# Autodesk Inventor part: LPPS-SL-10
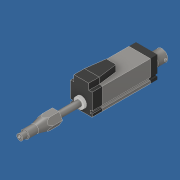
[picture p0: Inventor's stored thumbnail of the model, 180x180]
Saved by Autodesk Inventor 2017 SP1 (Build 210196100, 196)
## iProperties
Created: 2016-12
Part Number: LPPS-SL-10
Material: Stainless Steel
Document SubType Name: Modeling
Designer: JN
Density: 8 g/cm^3
Appearance: Stainless - Brushed
Author: JN
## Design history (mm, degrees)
sketch "Sketch1"
  geometry: C1 r 2.54 at (0, 0)
  constraints: 1 centre point, 1 other
  dimensions: "d0" = 5.08 diameter of C1
extrude "Extrusion1" new body sketch "Sketch1" distance "d1" = 4.572; taper "d2" = 0 deg
sketch "Sketch2"
  geometry: C1 r 3.48 at (0, 0)
  constraints: 1 centre point
  dimensions: "d3" = 6.9596 diameter of C1
extrude "Extrusion2" join sketch "Sketch2" distance "d4" = 8.2042; taper "d5" = 0 deg
workaxis "Work Axis1"
revolve "Revolution2" stored, may be unused: angle "d8" = 90 deg
sketch "Sketch7"
  geometry: L1 (-5.778, 0)-(-2.889, 5.004); L2 (-2.889, 5.004)-(2.889, 5.004); L3 (2.889, 5.004)-(5.778, 0); L4 (5.778, 0)-(2.889, -5.004); L5 (2.889, -5.004)-(-2.889, -5.004); L6 (-2.889, -5.004)-(-5.778, 0); L7 (0, 0)-(0, 8.469); L8 (-0.303, -0.272)-(8.166, -0.272); L9 (0, -3.48)-(0, 0)
  constraints: 18 end point, 3 perpendicular, 1 horizontal, 1 vertical alignment, 14 other
  dimensions: "d20" = 90 deg angle of L8 L7; "d23" = 10.0076 distance between parallel lines of L5 L2
extrude "Extrusion4" join sketch "Sketch7" distance "d21" = 18.03974; taper "d22" = 0 deg
sketch "Sketch8"
  geometry: L1 (3.48, -4.572)-(3.48, -12.776) reference; L2 (0, 1.416)-(0, -21.685); L3 (0, -12.776)-(0, -30.816) reference; L4 (0, 9.356)-(0, -46.226) reference; L5 (5.004, -30.816)-(-5.004, -30.816); L6 (5.004, -30.816)-(0, -30.816) reference; L7 (0, -30.816)-(-5.004, -30.816) reference; L8 (-5.004, -12.776)-(-5.004, -30.816) reference; L9 (-5.004, -30.816)-(-5.004, -12.776); L10 (4.859, -30.943)-(-0.272, -30.943); L11 (-3.48, -12.776)-(3.48, -12.776) reference; L12 (3.48, -4.572)-(3.48, -12.776) reference; L13 (3.48, -12.776)-(3.481, -12.776); L14 (3.481, -12.776)-(9.456, -38.286); L15 (3.481, -12.776)-(9.456, -12.776); L16 (9.456, -38.286)-(9.456, -12.776); A1 r 1.416 centre (0, 0) between (1.416, 0) and (-1.416, 0) reference; 1 further point
  constraints: 16 end point, 2 collinear, 1 horizontal, 1 perpendicular, 1 point on circle, 1 point on line, 1 vertical
revolve "Revolution9" sketch "Sketch8" stored, may be unused: angle "d35" = 90 deg
sketch "Sketch9"
  geometry: C1 r 2.54 at (0, 0)
  constraints: 1 centre point
  dimensions: "d36" = 5.08 diameter of C1
extrude "Extrusion5" join sketch "Sketch9" distance "d37" = 19.812 (= Stroke); taper "d38" = 0 deg
sketch "Sketch10"
  geometry: C1 r 2.54 at (0, 0) reference; C2 r 4.521 at (0, 0)
  constraints: 1 centre point, 1 coincident
  dimensions: "d39" = 9.0424 diameter of C2
extrude "Extrusion6" join sketch "Sketch10" distance "d40" = 2; taper "d41" = 0 deg
sketch "Sketch11"
  geometry: L1 (-9.143, 16.927)-(9.145, 16.927); L2 (9.145, -6.949)-(-9.143, -6.949); L3 (-9.143, -6.949)-(-9.143, 16.927); L4 (-5.778, 0)-(-2.889, -5.004) reference; L5 (5.778, 0)-(2.889, 5.004) reference; L6 (-5.778, 0)-(5.778, 0); L7 (2.889, 5.004)-(-2.889, 5.004) reference; L8 (0, 5.004)-(0, -5.004); L9 (-2.889, -5.004)-(2.889, -5.004) reference; L10 (9.145, -6.949)-(9.145, -4.663); L11 (9.145, -4.663)-(7.621, -4.663); L12 (7.621, -4.663)-(7.621, -2.377); L13 (7.621, -2.377)-(9.145, -2.377); L14 (9.145, 16.927)-(9.145, -2.377); L15 (9.145, -4.663)-(9.145, -6.949); L16 (-9.143, -2.377)-(-7.619, -2.377); L17 (-7.619, -2.377)-(-7.619, -4.663); L18 (-7.619, -4.663)-(-9.143, -4.663)
  constraints: 28 end point, 9 perpendicular, 4 parallel, 4 point on line, 2 horizontal, 2 midpoint
  dimensions: "d42" = 18.288 distance of L1.start L1.end; "d43" = 3.3655 distance from line of L3 L4.start; "d47" = 23.876 distance of L1.end L2.start; "d49" = 1.94564 distance between parallel lines of L2 L9; "d98" = 2.286 distance of L2.start L10.end; "d99" = 1.524 distance of L10.end L11.end; "d100" = 2.286 distance of L11.end L12.end; "d101" = 1.524 distance of L16.start L16.end
extrude "Extrusion7" join sketch "Sketch11" distance "d50" = 9; taper "d51" = 0 deg
sketch "Sketch12"
  geometry: L1 (-9.145, -6.949)-(-9.145, 16.927) reference; L2 (9.143, 16.927)-(9.143, -6.949) reference; L3 (9.143, -6.949)-(-9.145, -6.949) reference; L4 (-9.145, -6.949)-(9.143, -6.949); L5 (-9.145, 16.927)-(9.143, 16.927); L6 (-9.145, 16.927)-(-9.145, -6.949); L7 (-9.145, 16.927)-(9.143, 16.927) reference; L8 (-6.319, 16.927)-(-6.319, 11.593); L9 (6.318, 16.927)-(6.318, 11.593); L10 (-9.145, 11.593)-(-6.319, 11.593); L11 (6.318, 11.593)-(9.143, 11.593)
  constraints: 15 end point, 4 parallel, 2 perpendicular, 2 point on line, 1 collinear
  dimensions: "d52" = 23.876 distance between parallel lines of L4 L5; "d55" = 2.82575 distance between parallel lines of L8 L1; "d56" = 2.82575 distance between parallel lines of L9 L2; "d57" = 18.542 distance between parallel lines of L3 L10; "d58" = 18.542 distance between parallel lines of L3 L11
extrude "Extrusion8" cut sketch "Sketch12" distance "d59" = 9; taper "d60" = 0 deg
mirror "Mirror1"
sketch "Sketch13"
  geometry: L1 (9.145, 11.593)-(6.319, 11.593) reference; L2 (-6.319, 16.927)-(6.319, 16.927); L3 (6.319, 16.927)-(6.319, 11.593); L4 (6.319, 11.593)-(-6.319, 11.593); L5 (-6.319, 11.593)-(-6.319, 16.927)
  constraints: 8 end point, 2 parallel, 1 horizontal, 1 perpendicular
workplane "Work Plane1"
sketch "Sketch14"
  geometry: L1 (6.319, 16.927)-(-6.319, 16.927) reference; L2 (-4.109, 16.927)-(4.121, 16.927); L3 (4.121, 16.927)-(4.121, 11.558); L4 (4.121, 11.558)-(-4.109, 11.558); L5 (-4.109, 11.558)-(-4.109, 16.927); L6 (-6.319, 16.927)-(-6.319, 11.593) reference; L7 (6.319, 11.593)-(6.319, 16.927) reference; 1 further point
  constraints: 8 end point, 2 parallel, 2 perpendicular, 1 horizontal, 1 point on line
  dimensions: "d62" = 8.2296 distance of L3.end L4.end; "d63" = 2.2098 distance between parallel lines of L6 L5; "d65" = 2.6844 distance from line of point (0.006, 14.242) L1; "d66" = 4.1148 distance from line of L5 point (0.006, 14.242)
sketch "3D Sketch1"
loft "Loft1" sketch "3D Sketch1" dims "d67" = 0, "d68" = 90 deg, "d69" = 0, "d70" = 90 deg, "d71" = 0, "d72" = 90 deg
sketch "Sketch15"
  geometry: L1 (-6.319, 11.593)-(-9.143, 11.593) reference; L2 (9.145, -6.949)-(9.145, 11.593) reference; L3 (-9.143, 11.593)-(9.145, 11.593); L4 (9.145, -6.949)-(-9.143, -6.949); L5 (7.621, -2.377)-(9.145, -2.377) reference; L6 (9.145, -2.377)-(7.621, -2.377); L7 (7.621, -4.663)-(7.621, -2.377) reference; L8 (7.621, -2.377)-(7.621, -4.663); L9 (9.145, -4.663)-(7.621, -4.663) reference; L10 (7.621, -4.663)-(9.145, -4.663); L11 (-9.143, -2.377)-(-7.619, -2.377) reference; L12 (-7.619, -4.663)-(-9.143, -4.663) reference; L13 (-9.143, -4.663)-(-7.619, -4.663); L14 (-7.619, -2.377)-(-7.619, -4.663) reference; L15 (-7.619, -4.663)-(-7.619, -2.377); L16 (-9.143, 11.593)-(-9.143, -2.377) reference; L17 (-7.619, -2.377)-(-9.143, -2.377); L18 (9.145, 11.593)-(9.145, -2.377); L19 (9.145, -4.663)-(9.145, -6.949); L20 (-9.143, -6.949)-(-9.143, -4.663); L21 (-9.143, -2.377)-(-9.143, 11.593)
  constraints: 24 end point, 5 parallel, 5 perpendicular, 3 collinear, 1 horizontal
extrude "Extrusion9" new body sketch "Sketch15" distance "d73" = 40.8686 (= Body); taper "d74" = 0 deg
sketch "Sketch16"
  geometry: L1 (-9.143, 11.593)-(-9.143, -6.949) reference; L2 (-9.143, -6.949)-(9.145, -6.949) reference; L3 (-9.143, 11.593)-(9.145, 11.593); L4 (9.145, -6.949)-(-9.143, -6.949); L5 (7.621, -2.377)-(9.145, -2.377) reference; L6 (9.145, -2.377)-(7.621, -2.377); L7 (9.145, -4.663)-(7.621, -4.663) reference; L8 (7.621, -2.377)-(7.621, -4.663); L9 (7.621, -4.663)-(9.145, -4.663); L10 (-9.143, -2.377)-(-7.619, -2.377) reference; L11 (-9.143, -2.377)-(-7.619, -2.377); L12 (-7.619, -2.377)-(-7.619, -4.663) reference; L13 (-7.619, -2.377)-(-7.619, -4.663); L14 (-7.619, -4.663)-(-9.143, -4.663) reference; L15 (-7.619, -4.663)-(-9.143, -4.663); L16 (-9.143, -6.949)-(-9.143, -4.663); L17 (-9.143, -2.377)-(-9.143, 11.593); L18 (9.145, 11.593)-(9.145, -2.377); L19 (9.145, -4.663)-(9.145, -6.949)
  constraints: 24 end point, 5 parallel, 4 perpendicular, 3 collinear, 2 horizontal
extrude "Extrusion10" new body sketch "Sketch16" distance "d75" = 6.0071; taper "d76" = 0 deg
sketch "Sketch17"
  geometry: L1 (-9.143, 11.593)-(9.145, 11.593) reference; L2 (9.145, 11.593)-(9.145, -2.377) reference; L3 (9.145, -6.949)-(-9.143, -6.949) reference; L4 (-9.143, -6.949)-(-9.143, -4.663) reference; L5 (-9.143, -4.663)-(-7.619, -4.663) reference; L6 (-7.619, -4.663)-(-7.619, -2.377) reference; L7 (-7.619, -2.377)-(-9.143, -2.377) reference; L8 (-9.143, -2.377)-(-9.143, 11.593) reference; L9 (9.145, -2.377)-(7.621, -2.377) reference; L10 (7.621, -2.377)-(7.621, -4.663) reference; L11 (7.621, -4.663)-(9.145, -4.663) reference; L12 (9.145, -4.663)-(9.145, -6.949) reference; C1 r 2.54 at (0, 0) reference; C2 r 1.416 at (0, 0) reference; C3 r 4.051 at (0, 0)
  constraints: 1 centre point, 1 coincident
  dimensions: "d77" = 8.1026 diameter of C3
extrude "Extrusion11" new body sketch "Sketch17" distance "d78" = 5; taper "d79" = 0 deg
sketch "Sketch18"
  geometry: C1 r 1.416 at (0, 0) reference; C2 r 5 at (0, 0)
  constraints: 1 centre point, 1 coincident
  dimensions: "d80" = 10 diameter of C2
extrude "Extrusion12" new body sketch "Sketch18" distance "d81" = 8; taper "d82" = 0 deg
shell "Shell2" dims "d84" = 1.397
workaxis "Work Axis4"
workplane "Work Plane2"
sketch "Sketch19"
  geometry: L1 (-5, -8)-(5, -8) reference; L2 (0, -8)-(0, -6.095); 1 further point
  constraints: 2 end point, 1 coincident, 1 midpoint, 1 vertical
  dimensions: "d85" = 1.905 distance of L2.start L2.end
hole "Hole1" sketch "Sketch19" at (0, -6.095) diameter "d86" = 2.3876; stored, may be unused: countersink angle "d90" = 82 deg, drill point angle "d92" = 118 deg; dims "d87" = 19.05, "d88" = 9.525, "d89" = 6.35, "d91" = 25.4
body "Solid1"
sketch "Sketch3"
  geometry: L1 (-2.54, 0)-(2.54, 0) reference; L2 (1.416, 0)-(0, 0); L3 (0, 0)-(0, 1.416); A1 r 1.416 centre (0, 0) between (1.416, 0) and (0, 1.416)
  constraints: 4 end point, 2 point on circle, 1 centre point, 1 midpoint, 1 vertical
  dimensions: "d6" = 2.8321 diameter of A1
body "Solid2"
body "Solid3"
body "Solid4"
body "Solid5"
node "Project Cut Edges1"
other parameters: "Stroke" = 19.812 [user parameter; used in 1 equation term], "Body" = 40.8686 [user parameter; used in 1 equation term], "d53" = 5.334, "d61" = 16.51
